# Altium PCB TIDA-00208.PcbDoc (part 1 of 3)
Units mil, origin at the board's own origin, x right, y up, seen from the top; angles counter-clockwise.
Board outline 4724.41 x 3937.01 mil, 4 copper layers (Top Layer, MidLayer1, MidLayer2, Bottom Layer), stack 90 mil thick; 243 components, 132 nets, 667 pads, 234 vias.
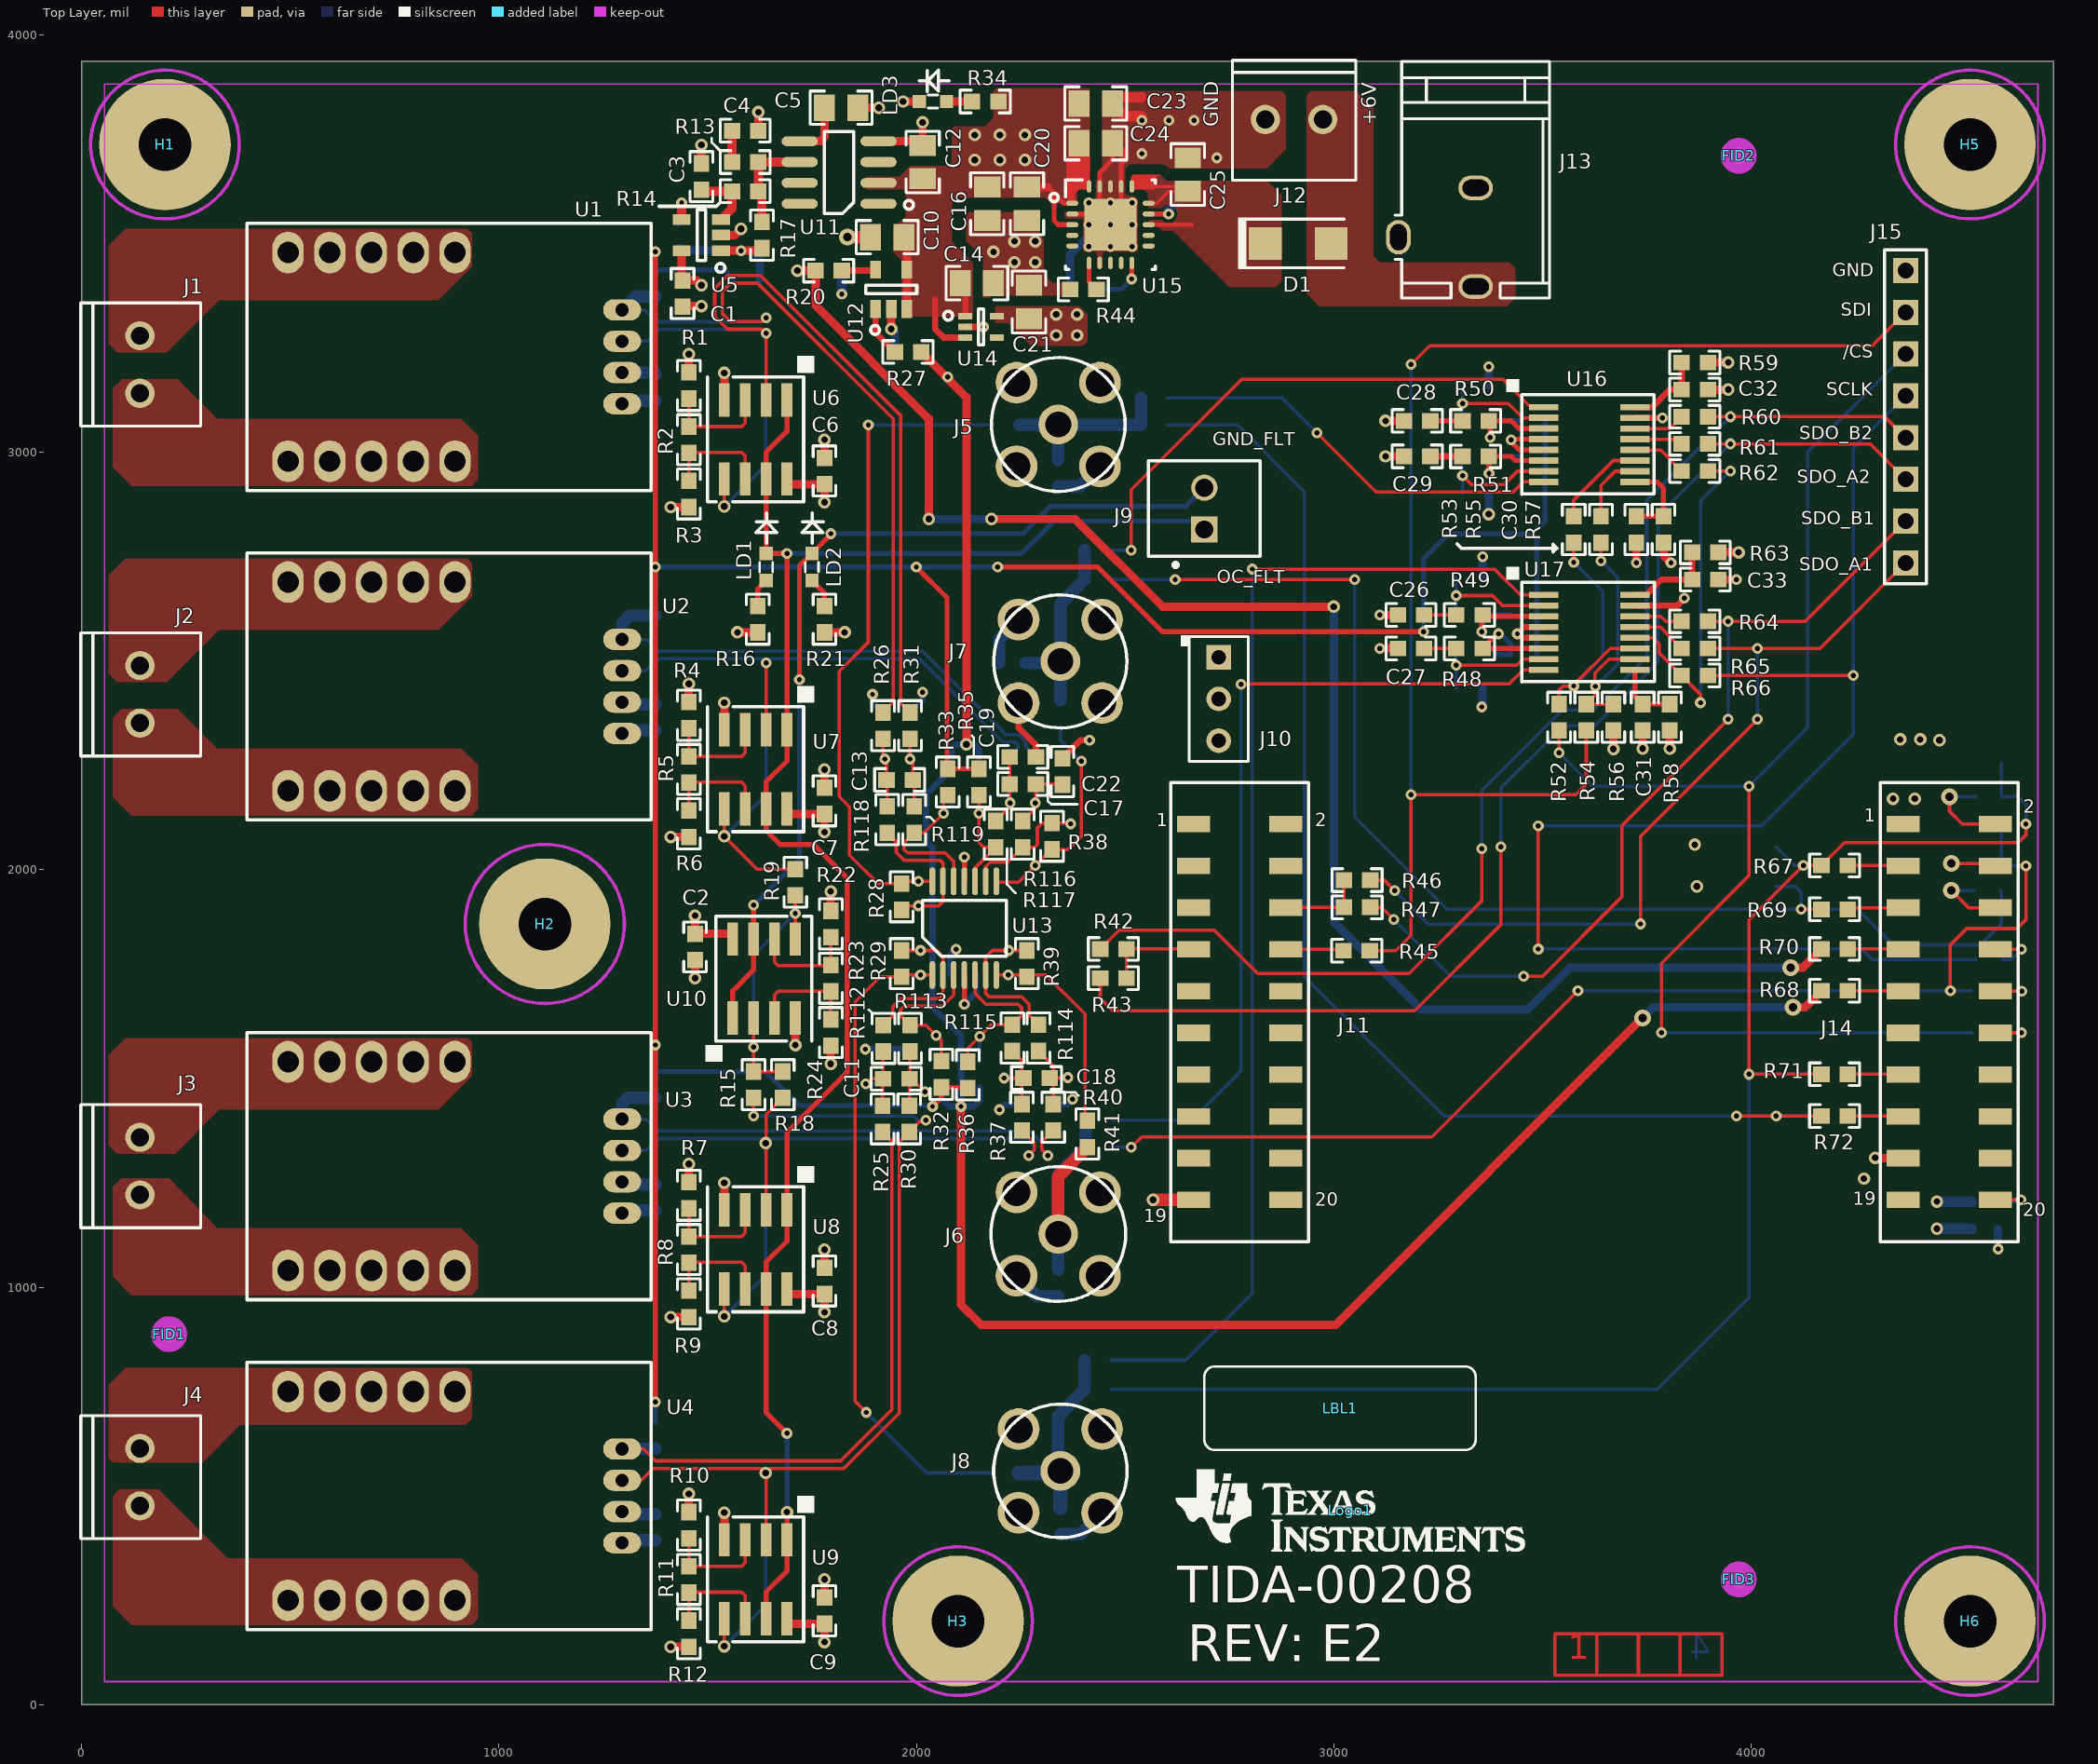
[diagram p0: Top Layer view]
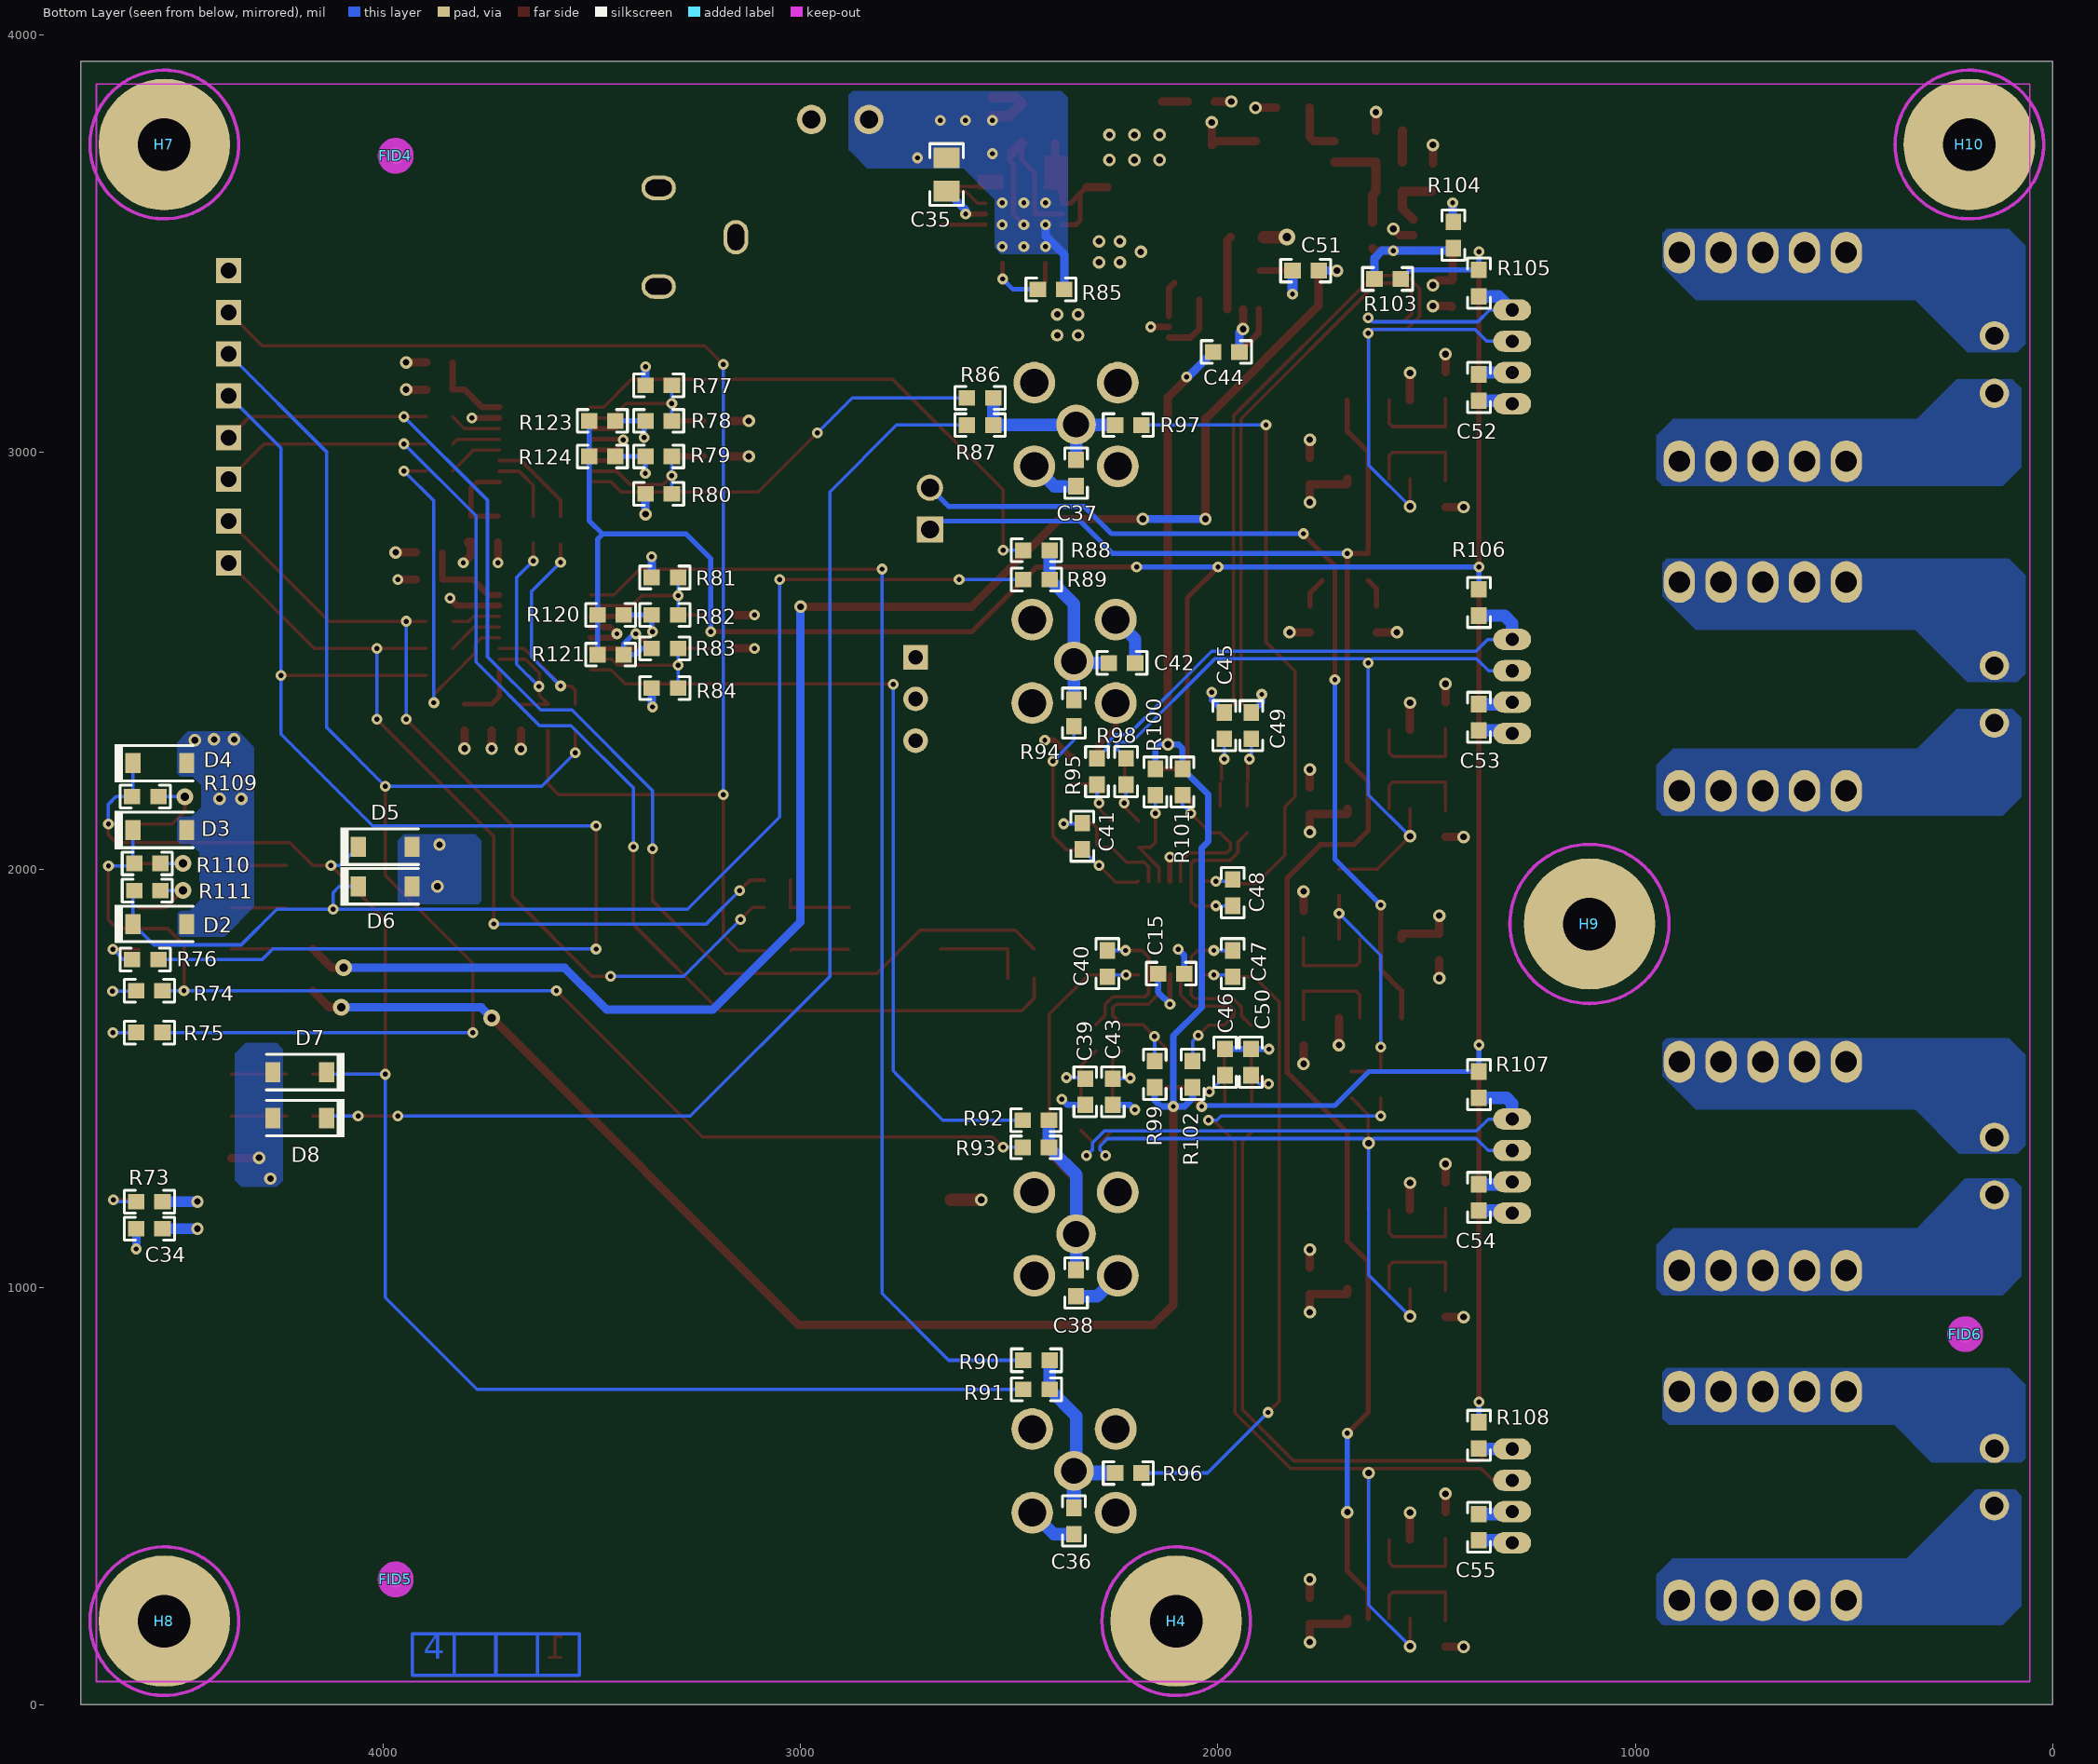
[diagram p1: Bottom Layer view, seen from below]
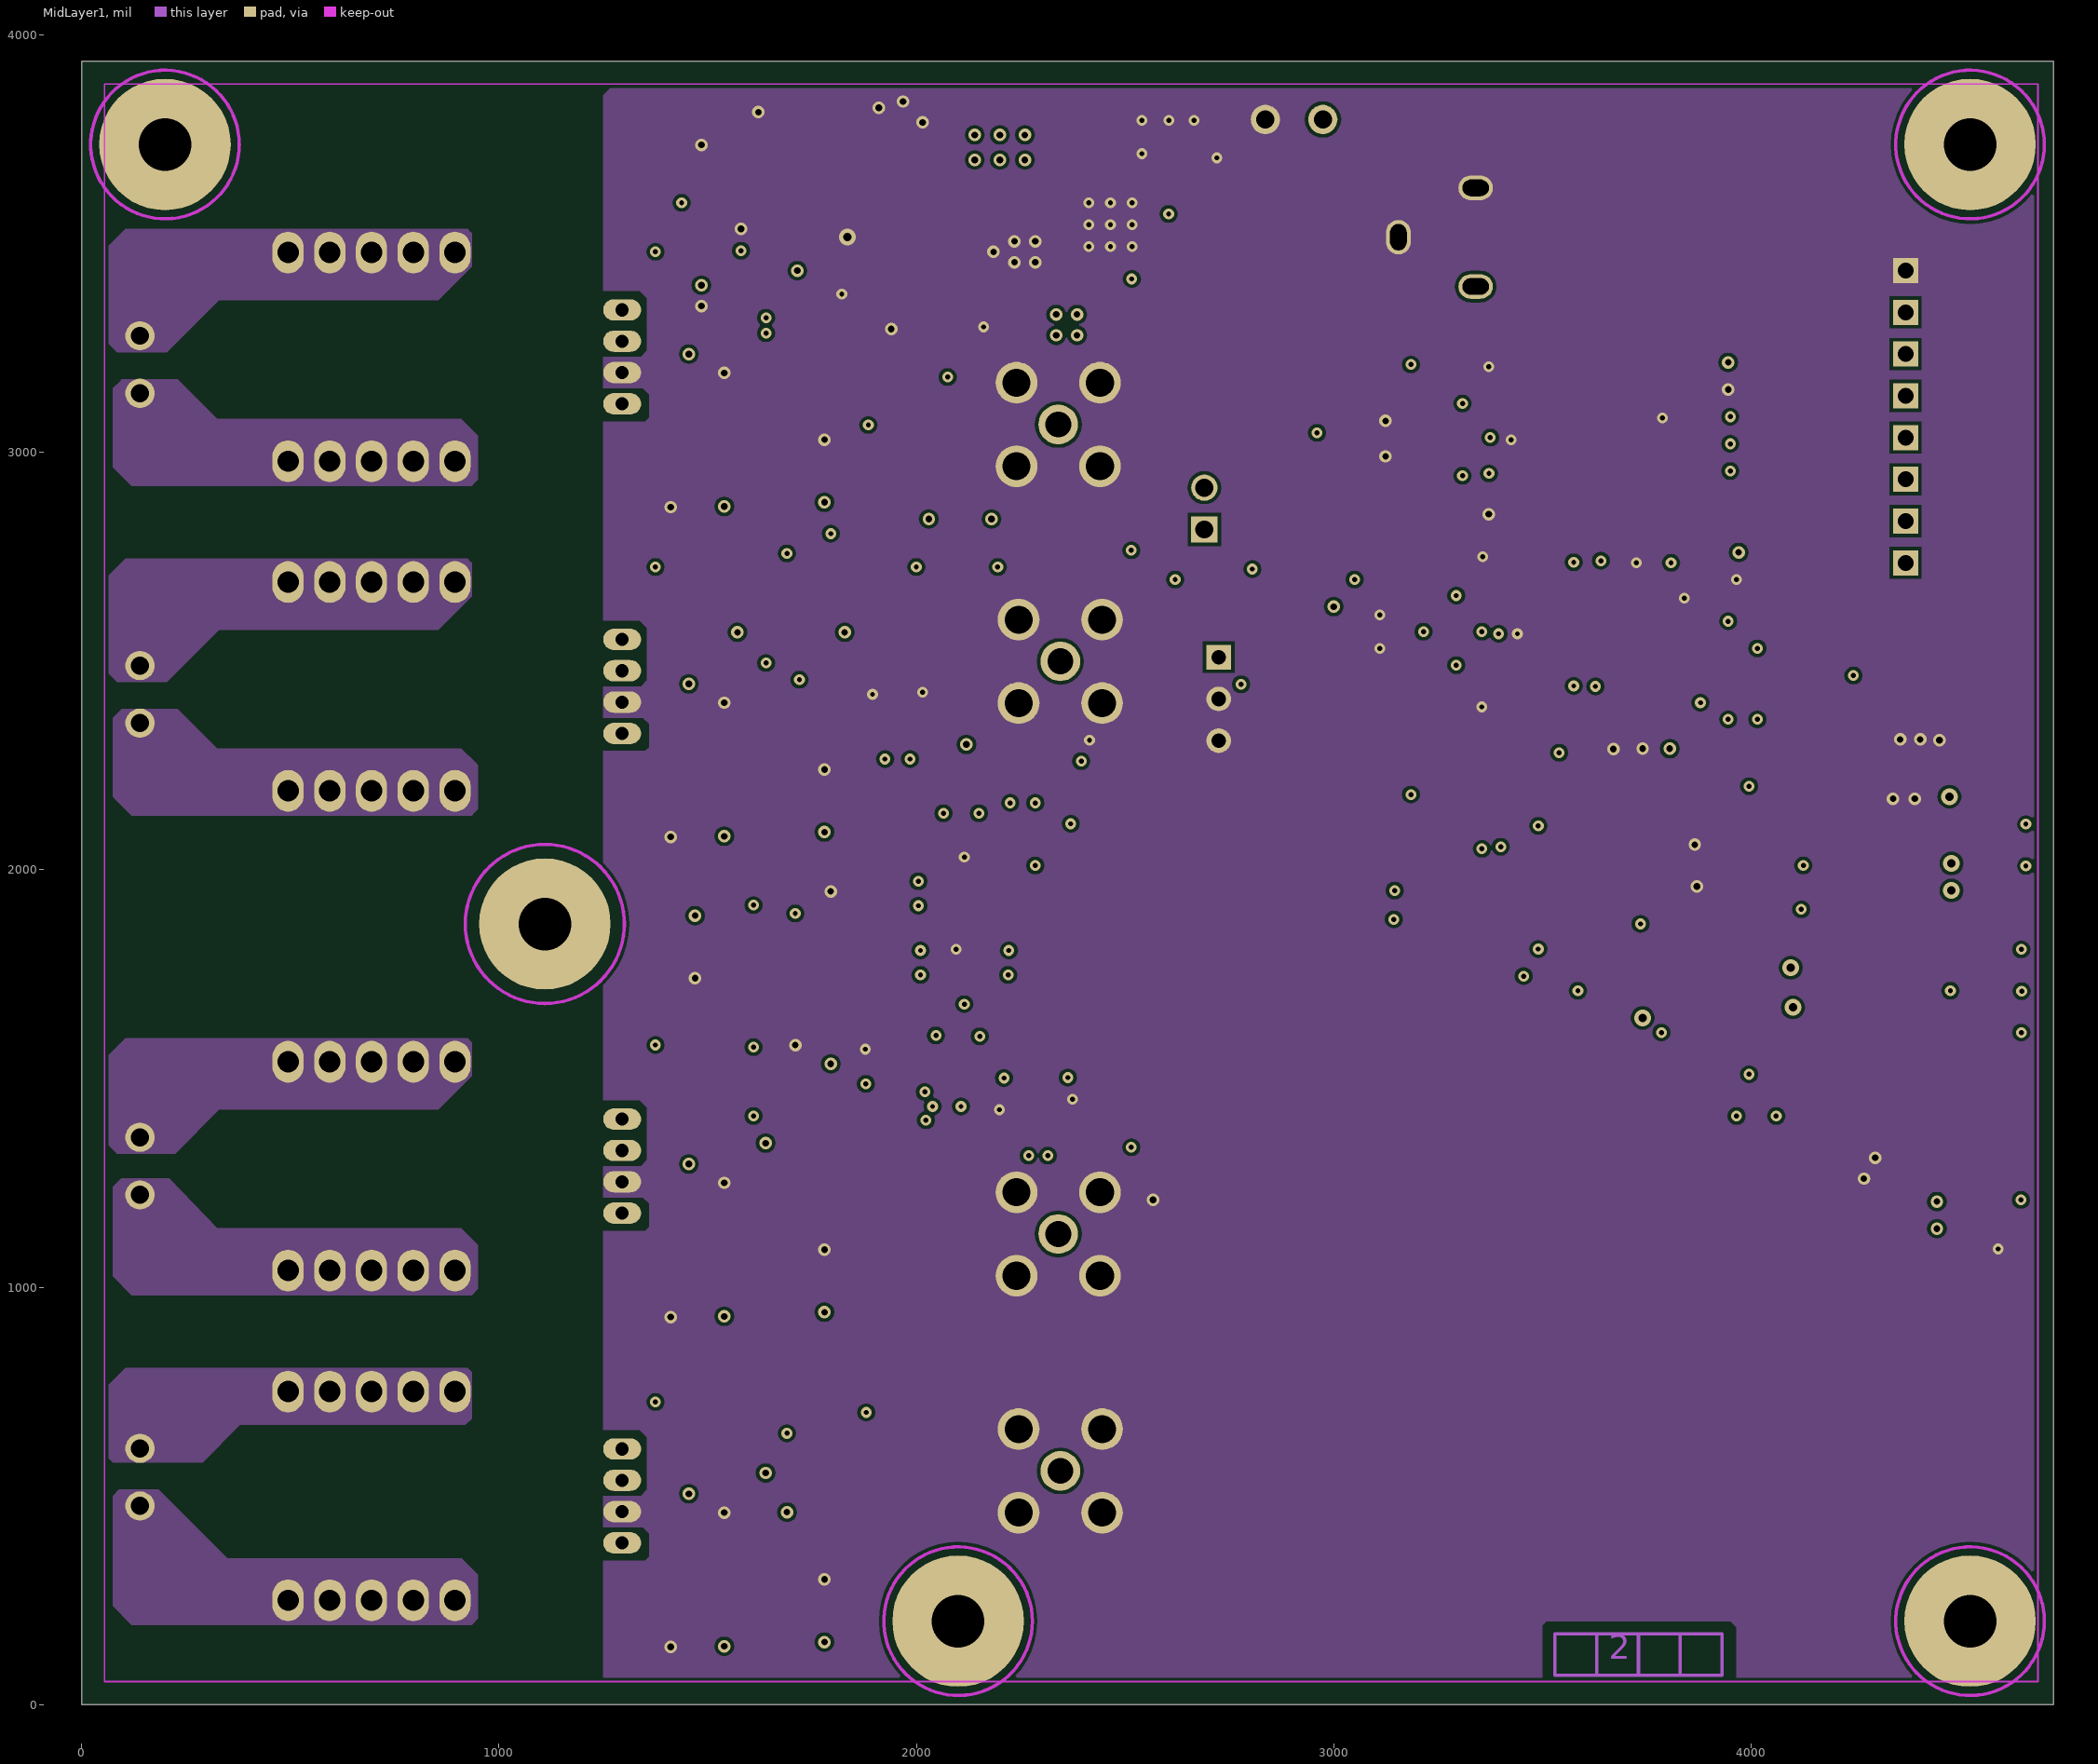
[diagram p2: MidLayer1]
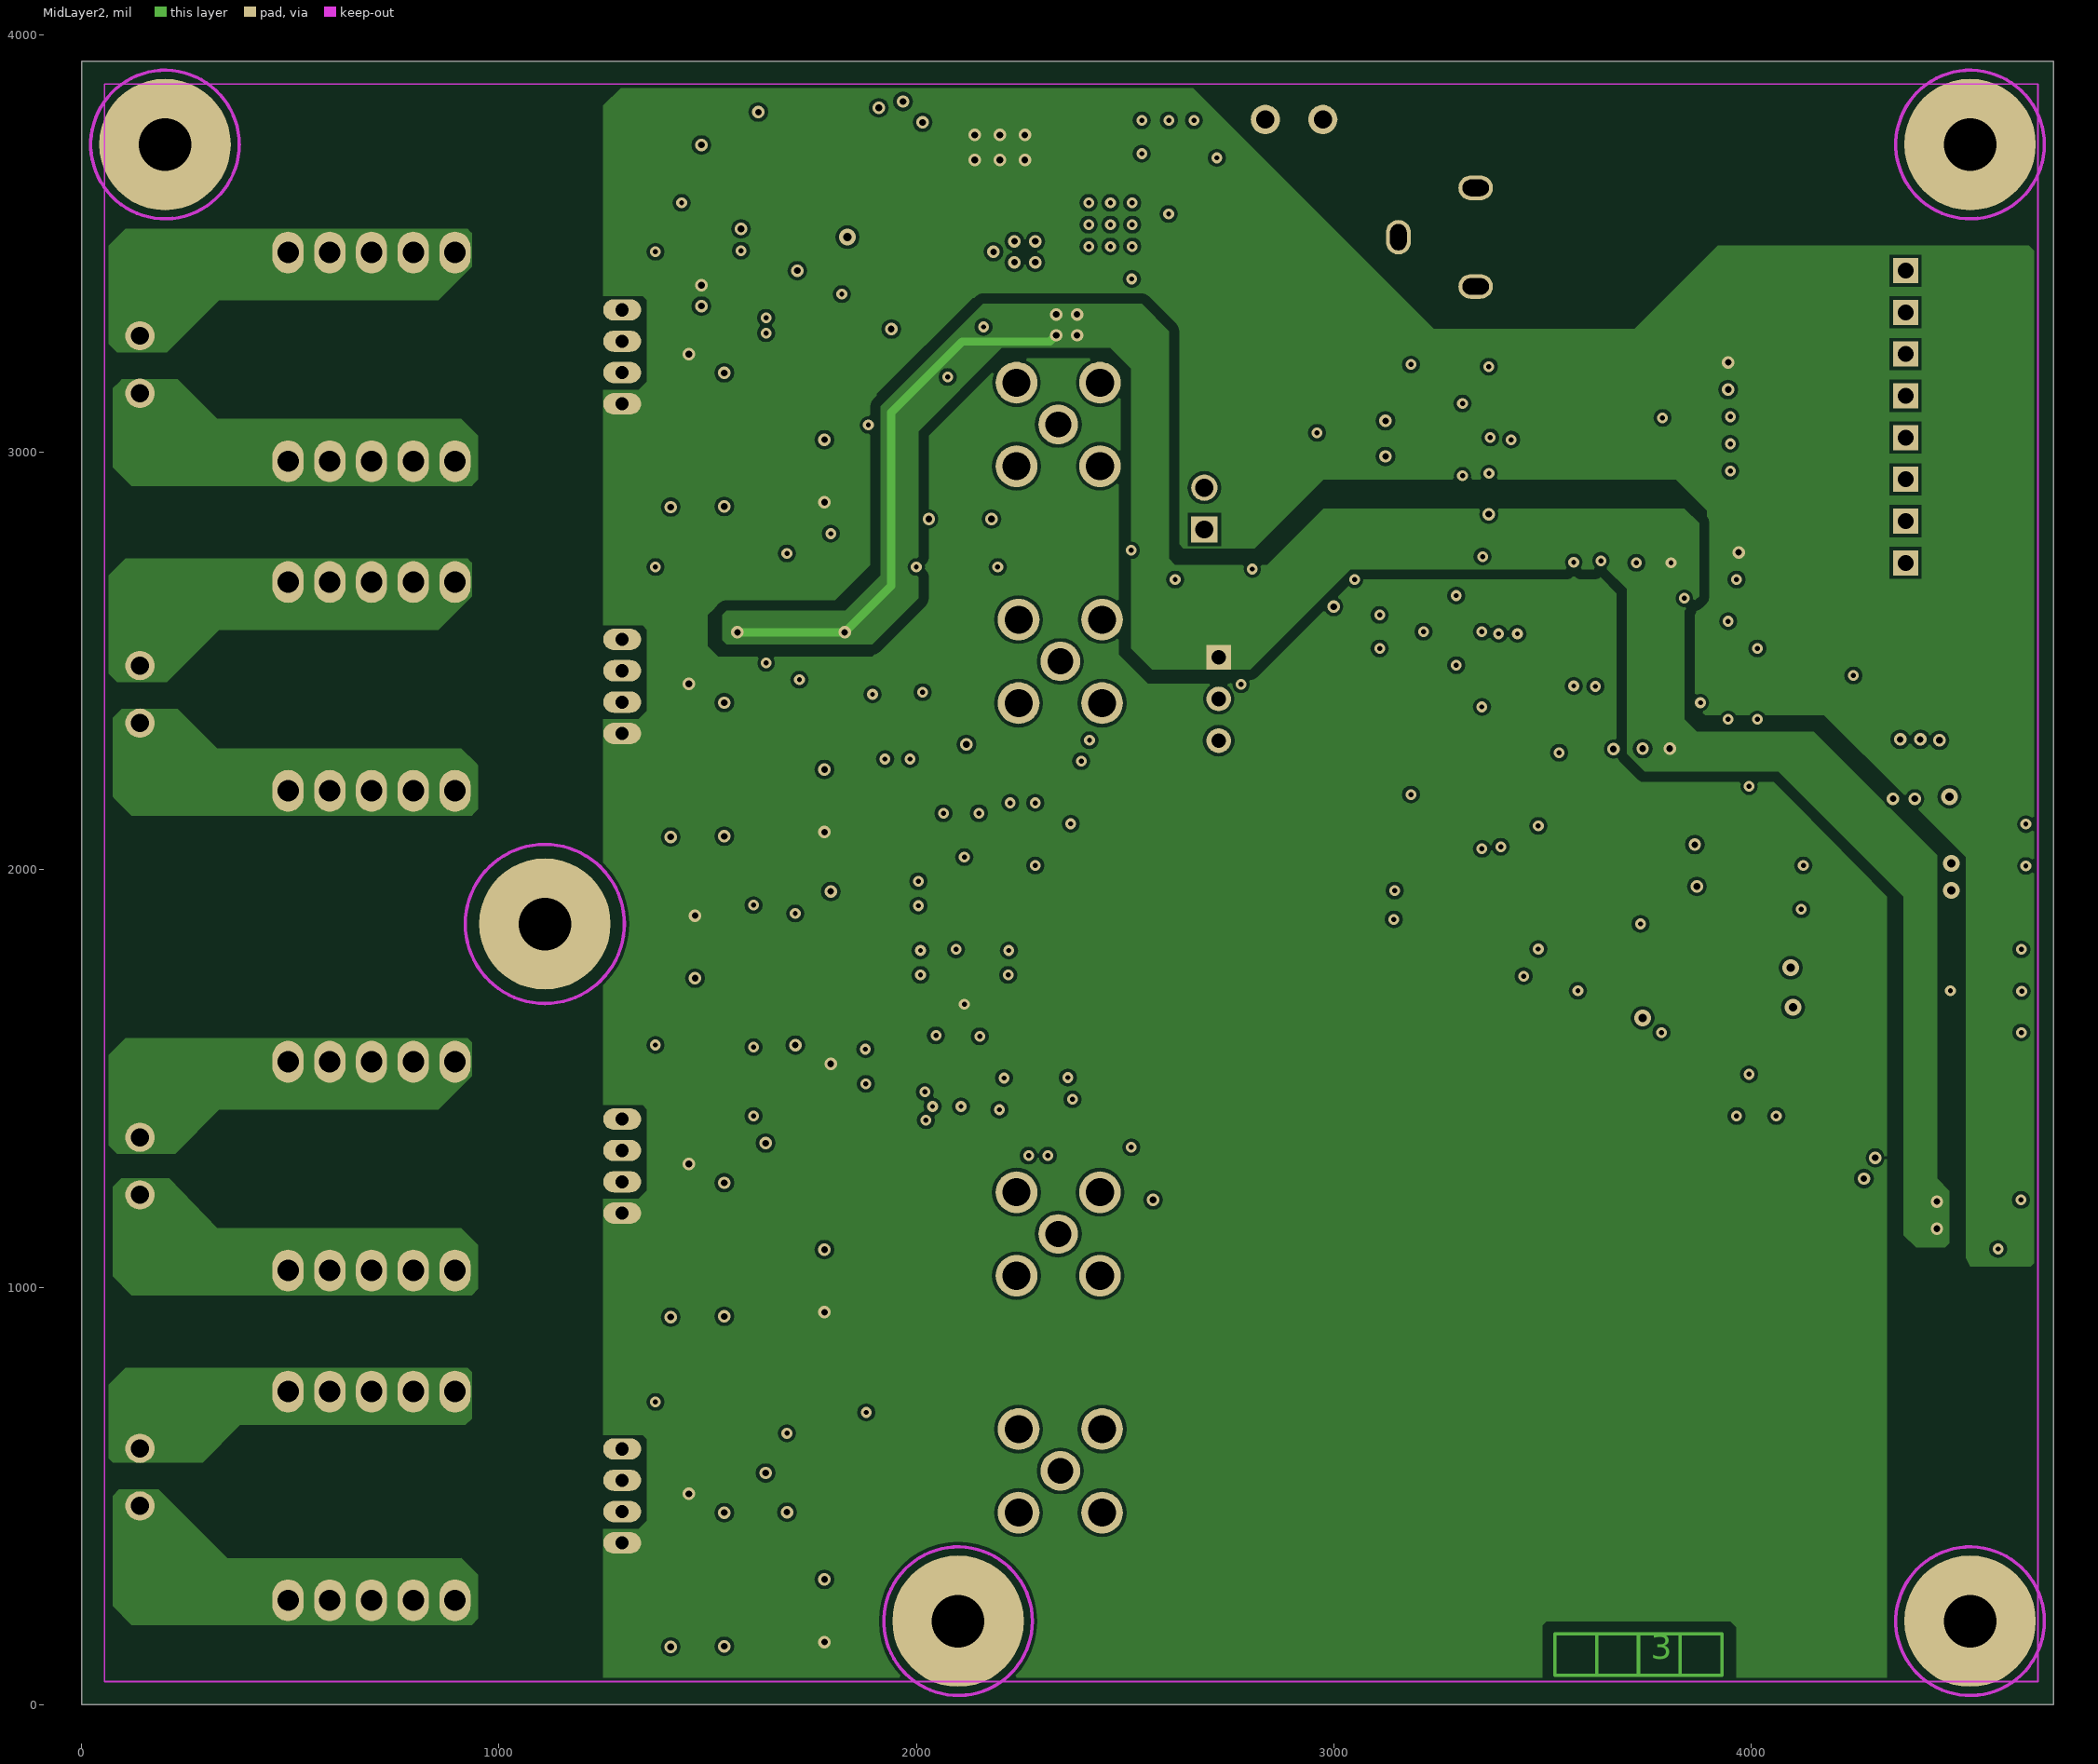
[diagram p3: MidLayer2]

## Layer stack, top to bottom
Top Layer: signal copper 1.4
Dielectric: core 59.2, FR-4, Dk 4.8
MidLayer1: signal copper 1.4
Dielectric: prepreg 12.6, FR-4, Dk 4.8
MidLayer2: signal copper 1.4
Dielectric: core 12.6, FR-4, Dk 4.8
Bottom Layer: signal copper 1.4

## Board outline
0,0 4724.41,0 4724.41,3937.01 0,3937.01

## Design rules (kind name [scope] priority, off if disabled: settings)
AcuteAngle [All] p1: minimum=4.50000000000000E+0001 checktracksonly=FALSE
AssemblyTestPointUsage [All] p1: valid=2
Clearance "Less Than 9 mils from PAD to PAD" [(InPadClass('Less than 9 Mil Clearance')) vs (InPadClass('All Pads'))] p1: gap=7
Clearance "SMT Pin Via" [IsVia vs IsSMTPin] p2: gap=8
Clearance "Via to Via" [IsVia vs IsVia] p3: gap=8
Clearance Clearance_Poly [InPolygon vs IsVia and IsVia and IsSMTPin and IsThruPin] p4: gap=15
Clearance "Poly to Poly" [InPolygon vs InPolygon] p5: gap=25
Clearance [All] p6: gap=8
ComponentClearance ComponentClearance_Shunt [InComponentClass('Header') vs InComponentClass('Shunt')] p1: gap=0 collisioncheckmode=3 verticalgap=0 showdistances=FALSE
ComponentClearance ComponentClearance_Logo [InComponentClass('Logo')] p2: gap=50 collisioncheckmode=3 verticalgap=10 showdistances=FALSE
ComponentClearance ComponentClearance_ScrewToNut [(HasFootprint('NY PMS 440 0025 PH')) vs (HasFootprint('Keystone_1902C'))] p3: gap=5 collisioncheckmode=3 verticalgap=10 showdistances=FALSE
ComponentClearance ComponentClearance_MountingHoles [InComponentClass('Mounting Holes')] p4: gap=250 collisioncheckmode=3 verticalgap=100000 showdistances=FALSE
ComponentClearance ComponentClearance_SmallPassives [HasFootprint('0201*') or HasFootprint('0402*') or HasFootprint('0508') or HasFootprint('0603*') or HasFootprint('0612') or HasFootprint('0805*') or HasFootprint('0815*') or HasFootprint('0830*') or HasFootprint('1206*') or HasFootprint('1210*') or HasFootprint('1808*') or HasFootprint('1812*') or HasFootprint('1825*') or HasFootprint('2010*') or HasFootprint('2220*') or HasFootprint('2225*') or HasFootprint('2512*') or HasFootprint('2728*') or HasFootprint('3518*') vs HasFootprint('0201*') or HasFootprint('0402*') or HasFootprint('0508') or HasFootprint('0603*') or HasFootprint('0612') or HasFootprint('0805*') or HasFootprint('0815*') or HasFootprint('0830*') or HasFootprint('1206*') or HasFootprint('1210*') or HasFootprint('1808*') or HasFootprint('1812*') or HasFootprint('1825*') or HasFootprint('2010*') or HasFootprint('2220*') or HasFootprint('2225*') or HasFootprint('2512*') or HasFootprint('2728*') or HasFootprint('3518*')] p5: gap=20 collisioncheckmode=3 verticalgap=10 showdistances=FALSE
ComponentClearance ComponentClearance_THtoSMT [IsThruComponent vs IsSMTComponent] p6: gap=100 collisioncheckmode=3 verticalgap=30 showdistances=FALSE
ComponentClearance ComponentClearance_THtoTH [IsThruComponent vs IsThruComponent] p7: gap=118.11 collisioncheckmode=3 verticalgap=30 showdistances=FALSE
ComponentClearance [All] p8: gap=40 collisioncheckmode=3 verticalgap=10 showdistances=FALSE
DiffPairsRouting DiffPair_CH3DiffPairsRouting [InDifferentialPair ('CH3')] p1: maxlimit=10 minlimit=10 mostfreqgap=10 maxuncoupledlength=500
DiffPairsRouting DiffPair_CH4DiffPairsRouting [InDifferentialPair ('CH4')] p2: maxlimit=10 minlimit=10 mostfreqgap=10 maxuncoupledlength=500
DiffPairsRouting DiffPair_CH2DiffPairsRouting [InDifferentialPair ('CH2')] p3: maxlimit=10 minlimit=10 mostfreqgap=10 maxuncoupledlength=500
DiffPairsRouting DiffPair_CH1DiffPairsRouting [InDifferentialPair ('CH1')] p4: maxlimit=10 minlimit=10 mostfreqgap=10 maxuncoupledlength=500
DiffPairsRouting [All] p5: maxlimit=100 minlimit=10 mostfreqgap=10 maxuncoupledlength=1000
FabricationTestPointUsage TestPointUsage [All] p1: valid=2 allowmultiple=FALSE
FabricationTestpoint Testpoint [All] p1: side=3 testpointundercomponent=TRUE minsize=40 maxsize=100 preferedsize=60 minholesize=0 maxholesize=40 preferedholesize=32 testpointgrid=1 allowsidetop=TRUE allowsidebottom=TRUE usegrid=TRUE gridtolerance=0.01
FanoutControl Fanout_LCC [IsLCC] p1: bgadir=Out bgaviamode=Centered fanoutstyle=Auto fanoutdirection=Alternating viagrid=1 // Fanout_LCC (Default Rule)
FanoutControl Fanout_BGA [IsBGA] p2: bgadir=Out bgaviamode=Centered fanoutstyle=Auto fanoutdirection=Alternating viagrid=1 // Fanout_BGA (Default Rule)
FanoutControl Fanout_Default [All] p4: bgadir=Out bgaviamode=Centered fanoutstyle=Auto fanoutdirection=Alternating viagrid=1 // Fanout_Default (Default Rule)
FanoutControl Fanout_Small [(CompPinCount < 5)] p5: bgadir=Out bgaviamode=Centered fanoutstyle=Auto fanoutdirection=OutThenIn viagrid=1 // Fanout_Small (Default Rule)
HoleSize [All] p1: absolutevalues=TRUE maxlimit=251 minlimit=8 maxpercent=80.000 minpercent=20.000
MatchedLengths DiffPair_CH3MatchedLengths [InDifferentialPair ('CH3')] p1: tolerance=500 checknetsindiffpair=TRUE checkdiffpairvsdiffpair=TRUE checkothers=TRUE
MatchedLengths DiffPair_CH4MatchedLengths [InDifferentialPair ('CH4')] p2: tolerance=500 checknetsindiffpair=TRUE checkdiffpairvsdiffpair=TRUE checkothers=TRUE
MatchedLengths DiffPair_CH2MatchedLengths [InDifferentialPair ('CH2')] p3: tolerance=500 checknetsindiffpair=TRUE checkdiffpairvsdiffpair=TRUE checkothers=TRUE
MatchedLengths DiffPair_CH1MatchedLengths [InDifferentialPair ('CH1')] p4: tolerance=500 checknetsindiffpair=TRUE checkdiffpairvsdiffpair=TRUE checkothers=TRUE
MinimumAnnularRing MinimumAnnularRing_ThermalPadVias [IsVia and InAnyComponent] p1: minimumring=6
MinimumAnnularRing [All] p2: minimumring=6
MinimumSolderMaskSliver MinimumSolderMaskSliver_Logo [InComponentClass('Logo') vs InComponentClass('Logo')] p1: minsoldermaskwidth=0.7
MinimumSolderMaskSliver [All] p2: minsoldermaskwidth=3.94
PlaneConnect [All] p1: planeconnectstyle=Relief reliefexpansion=10 reliefentries=4 reliefconductorwidth=10 reliefairgap=10
PolygonConnect [All] p1: connectstyle=Direct reliefconductorwidth=10 reliefentries=4 polygonreliefangle="90 Angle" airgapwidth=10
RoutingVias [All] p1: holewidth=12 width=26 viastyle="Through Hole" minholewidth=12 minwidth=26 maxholewidth=20 maxwidth=40
SMDToCorner [All] p1: distance=30000
SilkToSilkClearance [All] p1: silktosilkclearance=5
SilkscreenOverComponentPads [All] p1: minsilkscreentomaskgap=5
SolderMaskExpansion [All] p1: expansion=2.5
Width DiffPair_CH3Width [InDifferentialPair('CH3')] p1: maxlimit=100 minlimit=8 preferedwidth=8
Width DiffPair_CH4Width [InDifferentialPair('CH4')] p2: maxlimit=100 minlimit=8 preferedwidth=8
Width DiffPair_CH2Width [InDifferentialPair('CH2')] p3: maxlimit=100 minlimit=8 preferedwidth=8
Width DiffPair_CH1Width [InDifferentialPair('CH1')] p4: maxlimit=100 minlimit=8 preferedwidth=8
Width Width_PWR [InNetClass('PWR')] p5: maxlimit=100 minlimit=8 preferedwidth=15
Width [All] p6: maxlimit=100 minlimit=8 preferedwidth=8 checkconnectedcopper=TRUE
14 further rules are at their usual default settings.

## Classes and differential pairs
component class "Mounting Holes": H1 H2 H3 H5 H6
component class Logo: Logo1
component class Label: LBL1
component class FiducialMark: FID1 FID2 FID3 FID4 FID5 FID6
component class AssemblyNote: ZZ1 ZZ2 ZZ3 ZZ4

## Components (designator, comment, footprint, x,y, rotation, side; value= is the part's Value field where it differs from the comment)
C1 "C0603C104J4RACTU" 0603 1440,3380 r90 top (schematic designator C31)
C2 "C0603C104J4RACTU" 0603 1470,1815 r270 top (schematic designator C41)
C3 "C0603C104K8RACTU" 0603 1485,3660 r270 top (schematic designator C42)
C4 "EMK107BBJ106MA-T" 0603 1590,3770 r0 top (schematic designator C17)
C5 "C0805C105K8RACTU" 0805_HV 1820,3825 r0 top (schematic designator C15)
C6 "C0603C104J4RACTU" 0603 1780,2955 r90 top (schematic designator C54)
C7 "C0603C104J4RACTU" 0603 1780,2165 r90 top (schematic designator C40)
C8 "C0603C104J4RACTU" 0603 1780,1015 r90 top (schematic designator C14)
C9 "C0603C104J4RACTU" 0603 1780,225 r90 top (schematic designator C7)
C10 "C0805C105K8RACTU" 0805_HV 1930,3515 r180 top (schematic designator C28)
C11 "C0603H103J3GACTU" 0603 1952,1499 r180 top (schematic designator C47)
C12 "C0805C105K8RACTU" 0805_HV 2015,3695 r90 top (schematic designator C16)
C13 "C0603H103J3GACTU" 0603 1960,2215 r180 top (schematic designator C33)
C14 "C0805C105K8RACTU" 0805_HV 2145,3405 r0 top (schematic designator C18)
C15 "C0603C104J4RACTU" 0603 2112,1751 r0 bottom (schematic designator C2)
C16 "GRM21BR61C106KE15L" 0805_HV 2170,3595 r270 top (schematic designator C12)
C17 "C0603H103J3GACTU" 0603 2255,2205 r0 top (schematic designator C43)
C18 "C0603H103J3GACTU" 0603 2288,1501 r180 top (schematic designator C9)
C19 "C1608C0G1E562J" 0603 2255,2270 r0 top (schematic designator C45)
C20 "GRM21BR61C106KE15L" 0805_HV 2265,3595 r270 top (schematic designator C23)
C21 "C0805C105K8RACTU" 0805_HV 2270,3360 r90 top (schematic designator C19)
C22 "C1608C0G1E562J" 0603 2350,2235 r90 top (schematic designator C44)
C23 "GRM21BR61C106KE15L" 0805_HV 2430,3835 r0 top (schematic designator C22)
C24 "GRM21BR61C106KE15L" 0805_HV 2430,3740 r0 top (schematic designator C21)
C25 "GRM21BR61C106KE15L" 0805_HV 2650,3665 r90 top (schematic designator C5)
C26 "C1608X5R1E106M080AC" 0603 3185,2610 r180 top (schematic designator C4)
C27 "C1608X5R1E106M080AC" 0603 3185,2530 r0 top (schematic designator C10)
C28 "C1608X5R1E106M080AC" 0603 3200,3075 r180 top (schematic designator C25)
C29 "C1608X5R1E106M080AC" 0603 3200,2990 r0 top (schematic designator C26)
C30 "C1608X5R1E106M080AC" 0603 3725,2815 r270 top (schematic designator C27)
C31 "C1608X5R1E106M080AC" 0603 3740,2365 r270 top (schematic designator C11)
C32 "C1608X5R1E106M080AC" 0603 3865,3150 r0 top (schematic designator C24)
C33 "C1608X5R1E106M080AC" 0603 3890,2695 r0 top (schematic designator C3)
C34 "GRM188R71E105KA12D" 0603 4560,1140 r0 bottom (schematic designator C55)
C35 "C0805C105K8RACTU" 0805_HV 2650,3665 r270 bottom (schematic designator C20)
C36 "C0603C104J4RACTU" 0603 2345,440 r270 bottom (schematic designator C6)
C37 "C0603C104J4RACTU" 0603 2340,2950 r270 bottom (schematic designator C53)
C38 "C0603C104J4RACTU" 0603 2340,1010 r270 bottom (schematic designator C13)
C39 "C1608C0G1E562J" 0603 2318,1468 r270 bottom (schematic designator C35)
C40 "GRM1885C1E102JA01D" 0603 2265,1775 r90 bottom (schematic designator C8)
C41 "GRM1885C1E102JA01D" 0603 2325,2080 r90 bottom (schematic designator C34)
C42 "C0603C104J4RACTU" 0603 2230,2495 r180 bottom (schematic designator C39)
C43 "C1608C0G1E562J" 0603 2252,1468 r270 bottom (schematic designator C36)
C44 "C0603C104K8RACTU" 0603 1980,3240 r0 bottom (schematic designator C30)
C45 "C1608C0G1E562J" 0603 1985,2345 r90 bottom (schematic designator C52)
C46 "C1608C0G1E562J" 0603 1983,1539 r90 bottom (schematic designator C49)
C47 "GRM1885C1E102JA01D" 0603 1965,1775 r90 bottom (schematic designator C1)
C48 "GRM1885C1E102JA01D" 0603 1965,1945 r270 bottom (schematic designator C32)
C49 "C1608C0G1E562J" 0603 1920,2345 r90 bottom (schematic designator C51)
C50 "C1608C0G1E562J" 0603 1921,1539 r90 bottom (schematic designator C48)
C51 "C0603C104K8RACTU" 0603 1790,3435 r180 bottom (schematic designator C29)
C52 "GRM188R71E105KA12D" 0603 1375,3155 r270 bottom (schematic designator C38)
C53 "GRM188R71E105KA12D" 0603 1375,2365 r270 bottom (schematic designator C46)
C54 "GRM188R71E105KA12D" 0603 1375,1215 r270 bottom (schematic designator C37)
C55 "GRM188R71E105KA12D" 0603 1375,425 r270 bottom (schematic designator C50)
D1 "MBRA160T3G" SMA 2915,3500 r0 top
D2 "MMSZ5227B-7-F" SOD-123 4535,1870 r180 bottom
D3 "MMSZ5227B-7-F" SOD-123 4535,2095 r180 bottom
D4 "MMSZ5227B-7-F" SOD-123 4535,2255 r180 bottom
D5 "MMSZ5227B-7-F" SOD-123 3995,2055 r180 bottom
D6 "MMSZ5227B-7-F" SOD-123 3995,1960 r180 bottom
D7 "MMSZ5227B-7-F" SOD-123 4200,1515 r0 bottom
D8 "MMSZ5227B-7-F" SOD-123 4200,1405 r0 bottom
FID1 "Fiducial" Fiducial10-20 210,887.4 r90 top
FID2 "Fiducial" Fiducial10-20 3970,3710 r90 top (schematic designator FID3)
FID3 "Fiducial" Fiducial10-20 3970,300 r90 top (schematic designator FID2)
FID4 "Fiducial" Fiducial10-20 3970,3710 r90 bottom (schematic designator FID6)
FID5 "Fiducial" Fiducial10-20 3970,300 r90 bottom
FID6 "Fiducial" Fiducial10-20 210,887.4 r90 bottom (schematic designator FID4)
H1 "NY PMS 440 0025 PH" "NY PMS 440 0025 PH" 200,3737.01 r0 top (schematic designator H3)
H2 "NY PMS 440 0025 PH" "NY PMS 440 0025 PH" 1110,1870.08 r0 top (schematic designator H5)
H3 "NY PMS 440 0025 PH" "NY PMS 440 0025 PH" 2100,200 r0 top (schematic designator H1)
H4 "1902C" Keystone_1902C 2100,200 r180 bottom (schematic designator H6)
H5 "NY PMS 440 0025 PH" "NY PMS 440 0025 PH" 4524.41,3737.01 r0 top (schematic designator H2)
H6 "NY PMS 440 0025 PH" "NY PMS 440 0025 PH" 4524.41,200 r0 top (schematic designator H4)
H7 "1902C" Keystone_1902C 4524.41,3737.01 r180 bottom (schematic designator H9)
H8 "1902C" Keystone_1902C 4524.41,200 r180 bottom (schematic designator H7)
H9 "1902C" Keystone_1902C 1110,1870.08 r180 bottom (schematic designator H10)
H10 "1902C" Keystone_1902C 200,3737.01 r180 bottom (schematic designator H8)
J1 "1751248" CONN_1751248 140,3210 r270 top (schematic designator J7)
J2 "1751248" CONN_1751248 140,2420 r270 top (schematic designator J10)
J3 "1751248" CONN_1751248 140,1290 r270 top (schematic designator J5)
J4 "1751248" CONN_1751248 140,545 r270 top (schematic designator J1)
J5 "142-0701-201" Johnson_142-0701-20x 2340,3066.38 r0 top (schematic designator J12)
J6 "142-0701-201" Johnson_142-0701-20x 2340,1127.4 r0 top
J7 "142-0701-201" Johnson_142-0701-20x 2345,2498.98 r0 top (schematic designator J11)
J8 "142-0701-201" Johnson_142-0701-20x 2345,560 r0 top (schematic designator J2)
J9 "282834-2" TEC_282834-2 2690,2865 r90 top (schematic designator J8)
J10 "534237-1" CONN_534237-1 2724.41,2409.05 r90 top locked (schematic designator J3)
J11 "HEADER_NPTC202KFM" HEADER_NPTC202KFM 2774.41,1659.05 r270 top locked (schematic designator J2_J6)
J12 "1751248" CONN_1751248 2905,3797 r180 top (schematic designator J9)
J13 "PJ-102A" CONN_PJ-102A 3340,3515 r90 top (schematic designator J4)
J14 "HEADER_NPTC202KFM" HEADER_NPTC202KFM 4474.41,1659.05 r270 top locked (schematic designator J5_J1)
J15 "HEADER_1X8" HDR100_1X8 4370,2735 r90 top (schematic designator J14)
LBL1 "Size: 0.65\" x 0.20 \"" Label_650x200 3015,710 r180 top
LD1 "LED_LG L29K-G2J1-24-Z" LED0603AA 1640,2725 r270 top
LD2 "LED_LG L29K-G2J1-24-Z" LED0603AA 1750,2725 r270 top (schematic designator LD6)
LD3 "LED_LG L29K-G2J1-24-Z" LED0603AA 2040,3840 r0 top (schematic designator LD2)
Logo1 "Texas Instruments" TI_Stacked_SolderMask_Small 3040,465 r0 top
R1 "RC0603FR-073K3L" 0603 1455,3160 r90 top (schematic designator R98)
R2 "CRCW060320K0FKEA" 0603 1455,3030 r90 top (schematic designator R99)
R3 "RC0603FR-073K3L" 0603 1455,2900 r90 top (schematic designator R100)
R4 "RC0603FR-073K3L" 0603 1455,2370 r90 top (schematic designator R41)
R5 "CRCW060320K0FKEA" 0603 1455,2240 r90 top (schematic designator R44)
R6 "RC0603FR-073K3L" 0603 1455,2110 r90 top (schematic designator R50)
R7 "RC0603FR-073K3L" 0603 1455,1220 r90 top (schematic designator R19)
R8 "CRCW060320K0FKEA" 0603 1455,1090 r90 top (schematic designator R20)
R9 "RC0603FR-073K3L" 0603 1455,960 r90 top (schematic designator R22)
R10 "RC0603FR-073K3L" 0603 1455,430 r90 top (schematic designator R8)
R11 "CRCW060320K0FKEA" 0603 1455,300 r90 top (schematic designator R9)
R12 "RC0603FR-073K3L" 0603 1455,170 r90 top (schematic designator R11)
R13 "RC0603FR-071KL" 0603 1590,3695 r0 top (schematic designator R23)
R14 "CRCW06030000Z0EA" 0603 1590,3625 r0 top (schematic designator R72)
R15 "CRCW06031K00JNEA" 0603 1610,1485 r90 top (schematic designator R43)
R16 "CRCW060310K0JNEA" 0603 1620,2600 r270 top (schematic designator R7)
R17 "CRCW06030000Z0EA" 0603 1630,3520 r90 top (schematic designator R88)
R18 "CRCW06031K00JNEA" 0603 1680,1485 r90 top (schematic designator R48)
R19 "CRCW06031K00JNEA" 0603 1710,1970 r270 top (schematic designator R49)
R20 "CRCW06030000Z0EA" 0603 1790,3435 r0 top (schematic designator R81)
R21 "CRCW060310K0JNEA" 0603 1780,2600 r270 top (schematic designator R40)
R22 "RC0603FR-073K3L" 0603 1795,1870 r270 top (schematic designator R51)
R23 "CRCW060320K0FKEA" 0603 1795,1740 r270 top (schematic designator R45)
R24 "RC0603FR-073K3L" 0603 1795,1610 r270 top (schematic designator R42)
R25 "CRCW06031K50FKEA" 0603 1919,1403 r90 top (schematic designator R3)
R26 "CRCW06031K50FKEA" 0603 1920,2345 r270 top (schematic designator R91)
R27 "CRCW06030000Z0EA" 0603 1980,3240 r180 top (schematic designator R84)
R28 "CRCW06032K00FKEA" 0603 1965,1935 r90 top (schematic designator R89)
R29 "CRCW06032K00FKEA" 0603 1965,1775 r270 top (schematic designator R1)
R30 "CRCW06031K50FKEA" 0603 1983,1403 r90 top (schematic designator R2)
R31 "CRCW06031K50FKEA" 0603 1985,2345 r270 top (schematic designator R92)
R32 "CRCW06032K00FKEA" 0603 2060,1510 r90 top (schematic designator R82)
R33 "CRCW06032K00FKEA" 0603 2075,2210 r270 top (schematic designator R96)
R34 "CRCW060310K0JNEA" 0603 2165,3840 r0 top (schematic designator R85)
R35 "CRCW06032K00FKEA" 0603 2150,2210 r270 top (schematic designator R79)
R36 "CRCW06032K00FKEA" 0603 2123,1508.5 r90 top (schematic designator R76)
R37 "CRCW06031K50FKEA" 0603 2253,1407 r90 top (schematic designator R13)
R38 "CRCW06032K00FKEA" 0603 2325,2080 r270 top (schematic designator R33)
R39 "CRCW06032K00FKEA" 0603 2265,1775 r270 top (schematic designator R12)
R40 "CRCW06031K50FKEA" 0603 2328,1407 r90 top (schematic designator R14)
R41 "RT0603BRD0710RL" 0603 2410,1367 r270 top (schematic designator R17)
R42 "CRCW06030000Z0EA" 0603 2472,1810 r0 top (schematic designator R103)
R43 "CRCW06030000Z0EA" 0603 2472,1740 r0 top (schematic designator R102)
R44 "CRCW06030000Z0EA" 0603 2400,3390 r0 top (schematic designator R86)
R45 "CRCW06030000Z0EA" 0603 3055,1806 r180 top (schematic designator R61)
R46 "CRCW06030000Z0EA" 0603 3056,1975 r180 top (schematic designator R63)
R47 "CRCW06030000Z0EA" 0603 3056,1910 r180 top (schematic designator R66)
R48 "ERJ-3RSFR10V" 0603 3325,2530 r180 top (schematic designator R39)
R49 "ERJ-3RSFR10V" 0603 3325,2610 r0 top (schematic designator R10)
R50 "ERJ-3RSFR10V" 0603 3340,3075 r0 top (schematic designator R15)
R51 "ERJ-3RSFR10V" 0603 3340,2990 r180 top (schematic designator R29)
R52 "CRCW060347R0JNEA" 0603 3540,2365 r270 top (schematic designator R37)
R53 "CRCW06030000Z0EA" 0603 3575,2815 r90 top (schematic designator R28)
R54 "CRCW060347R0JNEA" 0603 3605,2365 r270 top (schematic designator R46)
R55 "CRCW06030000Z0EA" 0603 3640,2815 r90 top (schematic designator R31)
R56 "CRCW0603100KFKEA" 0603 3670,2365 r90 top (schematic designator R47)
R57 "CRCW06030000Z0EA" 0603 3790,2815 r270 top (schematic designator R32)
R58 "CRCW06030000Z0EA" 0603 3805,2365 r270 top (schematic designator R52)
R59 "CRCW06030000Z0EA" 0603 3865,3215 r0 top (schematic designator R4)
R60 "CRCW060347R0JNEA" 0603 3865,3085 r0 top (schematic designator R25)
R61 "CRCW060347R0JNEA" 0603 3865,3020 r0 top (schematic designator R26)
R62 "CRCW06030000Z0EA" 0603 3865,2955 r180 top (schematic designator R27)
R63 "CRCW06030000Z0EA" 0603 3890,2760 r0 top (schematic designator R5)
R64 "CRCW060347R0JNEA" 0603 3865,2595 r0 top (schematic designator R16)
R65 "CRCW060347R0JNEA" 0603 3865,2530 r0 top (schematic designator R18)
R66 "CRCW060347R0JNEA" 0603 3865,2465 r0 top (schematic designator R21)
R67 "CRCW06030000Z0EA" 0603 4200,2010 r180 top (schematic designator R36)
R68 "CRCW06030000Z0EA" 0603 4200,1710 r0 top (schematic designator R78)
R69 "CRCW06030000Z0EA" 0603 4200,1905 r0 top (schematic designator R62)
R70 "CRCW06030000Z0EA" 0603 4200,1810 r0 top (schematic designator R64)
R71 "CRCW06030000Z0EA" 0603 4200,1510 r180 top (schematic designator R104)
R72 "CRCW06030000Z0EA" 0603 4200,1410 r180 top (schematic designator R101)
R73 "CRCW06030000Z0EA" 0603 4560,1205 r180 bottom (schematic designator R53)
R74 "CRCW06030000Z0EA" 0603 4560,1710 r0 bottom (schematic designator R67)
R75 "CRCW06030000Z0EA" 0603 4560,1610 r0 bottom (schematic designator R68)
R76 "CRCW06030000Z0EA" 0603 4570,1785 r0 bottom (schematic designator R65)
R77 "CRCW06030000Z0EA" 0603 3340,3160 r0 bottom (schematic designator R24)
R78 "CRCW06030000Z0EA" 0603 3340,3075 r0 bottom (schematic designator R106)
R79 "CRCW06030000Z0EA" 0603 3340,2990 r0 bottom (schematic designator R108)
R80 "CRCW06030000Z0EA" 0603 3340,2900 r0 bottom (schematic designator R30)
R81 "CRCW06030000Z0EA" 0603 3325,2700 r0 bottom (schematic designator R59)
R82 "CRCW06030000Z0EA" 0603 3325,2610 r0 bottom (schematic designator R105)
R83 "CRCW06030000Z0EA" 0603 3325,2530 r0 bottom (schematic designator R107)
R84 "CRCW06030000Z0EA" 0603 3325,2435 r0 bottom (schematic designator R60)
R85 "CRCW06030000Z0EA" 0603 2400,3390 r180 bottom (schematic designator R87)
R86 "CRCW06030000Z0EA" 0603 2570,3130 r0 bottom (schematic designator R93)
R87 "CRCW06030000Z0EA" 0603 2570,3065 r0 bottom (schematic designator R94)
R88 "CRCW06030000Z0EA" 0603 2435,2765 r0 bottom (schematic designator R74)
R89 "CRCW06030000Z0EA" 0603 2435,2695 r0 bottom (schematic designator R56)
R90 "CRCW06030000Z0EA" 0603 2435,825 r0 bottom (schematic designator R57)
R91 "CRCW06030000Z0EA" 0603 2435,755 r0 bottom (schematic designator R58)
R92 "CRCW06030000Z0EA" 0603 2436.5,1400 r0 bottom (schematic designator R54)
R93 "CRCW06030000Z0EA" 0603 2436.5,1335 r0 bottom (schematic designator R55)
R94 "RT0603BRD0710RL" 0603 2345,2375 r90 bottom (schematic designator R38)
R95 "CRCW06031K50FKEA" 0603 2290,2235 r270 bottom (schematic designator R35)
R96 "RT0603BRD0710RL" 0603 2215,555 r0 bottom (schematic designator R6)
R97 "RT0603BRD0710RL" 0603 2215,3065 r0 bottom (schematic designator R95)
R98 "CRCW06031K50FKEA" 0603 2220,2235 r270 bottom (schematic designator R34)
R99 "CRCW06032K00FKEA" 0603 2151.54,1510 r90 bottom (schematic designator R77)
R100 "CRCW06032K00FKEA" 0603 2150,2210 r270 bottom (schematic designator R80)
R101 "CRCW06032K00FKEA" 0603 2085,2210 r270 bottom (schematic designator R97)
R102 "CRCW06032K00FKEA" 0603 2061,1510 r90 bottom (schematic designator R83)
R103 "CRCW06030000Z0EA" 0603 1593.5,3415 r0 bottom (schematic designator R71)
R104 "CRCW06030000Z0EA" 0603 1436,3520 r90 bottom (schematic designator R70)
R105 "CRCW06030000Z0EA" 0603 1375,3405 r90 bottom (schematic designator R90)
R106 "CRCW06030000Z0EA" 0603 1375,2640 r90 bottom (schematic designator R73)
R107 "CRCW06030000Z0EA" 0603 1375,1485 r90 bottom (schematic designator R69)
R108 "CRCW06030000Z0EA" 0603 1375,645 r90 bottom (schematic designator R75)
R109 "CRCW06030000Z0EA" 0603 4570,2175 r180 bottom
R110 "CRCW06030000Z0EA" 0603 4565,2015 r180 bottom
R111 "CRCW06030000Z0EA" 0603 4565,1950 r180 bottom
R112 "CRCW06030000Z0EA" 0603 1921,1596 r270 top
R113 "CRCW06030000Z0EA" 0603 1985,1596 r270 top
R114 "CRCW06030000Z0EA" 0603 2293,1597 r270 top
R115 "CRCW06030000Z0EA" 0603 2230,1597 r270 top
R116 "CRCW06030000Z0EA" 0603 2255,2085 r90 top
R117 "CRCW06030000Z0EA" 0603 2190,2085 r90 top
R118 "CRCW06030000Z0EA" 0603 1930,2120 r90 top
R119 "CRCW06030000Z0EA" 0603 1995,2120 r90 top
R120 "CRCW06030000Z0EA" 0603 3455,2610 r0 bottom
R121 "CRCW06030000Z0EA" 0603 3455,2515 r0 bottom
R123 "CRCW06030000Z0EA" 0603 3475,3075 r0 bottom
R124 "CRCW06030000Z0EA" 0603 3475,2990 r0 bottom
U1 "SENSOR_CKSR X-NP" "CKSR X-NP" 895,3228.35 r0 top (schematic designator U13)
U2 "SENSOR_CKSR X-NP" "CKSR X-NP" 895,2438.98 r0 top (schematic designator U14)
U3 "SENSOR_CKSR X-NP" "CKSR X-NP" 895,1290 r0 top (schematic designator U7)
U4 "SENSOR_CKSR X-NP" "CKSR X-NP" 895,500 r0 top (schematic designator U3)
U5 "OPA322AIDBVR" DBV0005A_N 1485,3520 r180 top (schematic designator U12)
U6 "TLC372" SO8 1615,3030 r270 top (schematic designator U17)
U7 "TLC372" SO8 1615,2240 r270 top (schematic designator U15)
U8 "TLC372" SO8 1615,1090 r270 top
U9 "TLC372" SO8 1615,300 r270 top (schematic designator U4)
U10 "TLC372" SO8 1635,1740 r90 top (schematic designator U16)
U11 "REF5025AID" D0008A_N 1815,3670 r180 top (schematic designator U9)
U12 "REF2033DBV" DBV0005A_N 1940,3390 r90 top (schematic designator U6)
U13 "OPA4322AIPW" PW0014A_N 2115,1860 r90 top (schematic designator U1)
U14 "TLV70033DCKR" DCK0005A_N 2155,3300 r0 top (schematic designator U10)
U15 "TPS7A4700RGW" RGW0020A 2465,3545 r0 top (schematic designator U5)
U16 "ADS7853" PW16 3610,3020 r0 top (schematic designator U11)
U17 "ADS7853" PW16 3610,2570 r0 top (schematic designator U2)
ZZ1 "These assemblies must be clean and free from flux and all contaminants. Use of no clean flux is not acceptable." AssemblyNote 315,4475 r0 top (schematic designator ZZ3)
ZZ2 "This Assembly Note is for PCB labels only" AssemblyNoteLabel 320,4640 r0 top (schematic designator ZZ1)
ZZ3 "These assemblies are ESD sensitive, ESD precautions shall be observed." AssemblyNote 320,4560 r0 top (schematic designator ZZ2)
ZZ4 "These assemblies must comply with workmanship standards IPC-A-610 Class 2, unless otherwise specified." AssemblyNote 320,4380 r0 top

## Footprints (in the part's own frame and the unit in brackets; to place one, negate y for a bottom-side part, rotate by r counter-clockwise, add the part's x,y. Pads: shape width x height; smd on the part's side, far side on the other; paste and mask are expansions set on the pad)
0603 [mm] "0603 from SM-752 data"
  rect 1x0.95 smd: 1(-0.8,0) 2(0.8,0)
  silkscreen extent -1.52,-0.69 1.52,0.69, body extent -0.87,-0.47 0.87,0.47, height 0.85
0805_HV [mil] "0805 with 30mil clearance between pads"
  rect 50x63 smd: 1(-40,0) 2(40,0)
  silkscreen extent -74,-40 74,40, body extent -43,-29 43,29, height 43
AssemblyNote [mil] "Assembly Note"
AssemblyNoteLabel [mil] "Assembly Note for PCB Labels"
"CKSR X-NP" [mm] "CURRENT SENSOR MOD"
  oval 1.9x2.54 hole 1.3: 1(-0.005,-6.35) 2(-2.545,-6.35) 3(-5.085,-6.35) 4(-7.625,-6.35) 5(-10.165,-6.35) 6(-10.165,6.35) 7(-7.625,6.35) 8(-5.085,6.35) 9(-2.545,6.35) 10(-0.005,6.35)
  oval 2.3x1.3 hole 0.8: 11(10.165,2.857) 12(10.165,0.953) 13(10.165,-0.953) 14(10.165,-2.857)
  silkscreen extent -12.66,-8.13 11.94,8.13, body extent -12.66,-6.7 9.25,6.7, height 16
CONN_534237-1 [mm] "TE Connectivity"
  rect 1.5x1.5 hole 0.889: 1(2.54,0)
  round 1.5 hole 0.889: 2(0,0) 3(-2.54,0)
  silkscreen extent -3.8,-1.8 3.88,2.3, body extent -3.81,-1.78 3.81,1.78, height 8.65
CONN_1751248 [mil] "Phoenix Contact"
  round 70 hole 43.31: 1(-68.9,0) 2(68.9,0)
  silkscreen extent -148,-142 148,146, body extent -148,-142 148,146, height 335
CONN_PJ-102A [mm] "CUI INC"
  oval 1.5x2.1 hole 1 slot 1.6 at 90 deg: 1(-3,0) 2(3,0)
  oval 2.1x1.5 hole 1 slot 1.6 at 0 deg: 3(0,4.7)
  silkscreen extent -3.7,-4.5 10.7,4.9, body extent -3.7,-4.5 10.7,4.9, height 11.02
D0008A_N [mm] "SOIC, 8-Leads, Body 4.9x3.9mm, Pitch 1.27mm, IPC Medium Density"
  oval 2.2x0.6 smd: 1(-2.4,1.905) 2(-2.4,0.635) 3(-2.4,-0.635) 4(-2.4,-1.905) 5(2.4,-1.905) 6(2.4,-0.635) 7(2.4,0.635) 8(2.4,1.905)
  silkscreen extent -0.9,-2.5 0.9,2.5, body extent -3,-2.45 3,2.45, height 1.63
DBV0005A_N [mm] "SOT23, 5-Leads, Body 2.9x1.6mm, Pitch 0.95mm, Lead Span 2.8mm, IPC Medium Density"
  rect 1.1x0.65 smd: 1(-1.2,0.95) 2(-1.2,0) 3(-1.2,-0.95) 4(1.2,-0.95) 5(1.2,0.95)
  silkscreen extent -0.25,-1.55 0.25,1.55, body extent -1.42,-1.46 1.42,1.46, height 1.08
DCK0005A_N [mm] "SOT353, 5-Leads, Body 2x1.3mm, Pitch 0.65mm, Lead Span 2.1mm, IPC Medium Density"
  rect 0.85x0.4 smd: 1(-0.95,0.65) 2(-0.95,0) 3(-0.95,-0.65) 4(0.95,-0.65) 5(0.95,0.65)
  silkscreen extent -0.15,-1.1 0.15,1.1, body extent -1.14,-1 1.14,1, height 0.94
Fiducial10-20 [mm]
  round 1 smd mask+0.5: 1(0,0)
  Top Layer keep-out circle w1.178: c0,0 r0.5
HDR100_1X8 [mil]
  rect 60x60 hole 38: 1(0,0) 2(100,0) 3(200,0) 4(300,0) 5(400,0) 6(500,0) 7(600,0) 8(700,0)
HEADER_NPTC202KFM [mm]
  rect 1x2 smd: 1(-11.43,-2.807) 2(-11.43,2.807) 3(-8.89,-2.807) 4(-8.89,2.807) 5(-6.35,-2.807) 6(-6.35,2.807) 7(-3.81,-2.807) 8(-3.81,2.807) 9(-1.27,-2.807) 10(-1.27,2.807) 11(1.27,-2.807) 12(1.27,2.807) 13(3.81,-2.807) 14(3.81,2.807) 15(6.35,-2.807) 16(6.35,2.807) 17(8.89,-2.807) 18(8.89,2.807) 19(11.43,-2.807) 20(11.43,2.807)
Johnson_142-0701-20x [mil] "Johnson Components recommended land pattern"
  round 95 hole 62: 1(0,0)
  round 100 hole 67: 2(100,100) 3(100,-100) 4(-100,-100) 5(-100,100)
  body extent -156,-156 156,156, height 375
Keystone_1902C [mil] "Hex Standoff, 4-40 threaded, nylon"
  round 1 on Mech4: 0(0,0)
  body extent -145,-126 146,126, height 501
Label_650x200 [mil] "Thermal Transfer Label"
  round 1 on Mech13: 0(0,0)
  silkscreen extent -325,-100 325,100, body extent -326,-101 326,101, height 1
LED0603AA [mil]
  rect 32x32 smd: 1(-32.48,0) 2(32.48,0)
  silkscreen extent -129,-24 11,27
"NY PMS 440 0025 PH" [mm] "4-40 nylon screw and mounting hole"
  round 8 hole 3.2: 1(0,0)
  body extent -3.3,-3.3 3.3,3.3, height 2.69
PW0014A_N [mm] "TSOP, 14-Leads, Body 5x4.4mm, Pitch 0.65mm, IPC Medium Density"
  oval 1.7x0.35 smd: 1(-2.85,1.95) 2(-2.85,1.3) 3(-2.85,0.65) 4(-2.85,0) 5(-2.85,-0.65) 6(-2.85,-1.3) 7(-2.85,-1.95) 8(2.85,-1.95) 9(2.85,-1.3) 10(2.85,-0.65) 11(2.85,0) 12(2.85,0.65) 13(2.85,1.3) 14(2.85,1.95)
  silkscreen extent -1.7,-2.55 1.7,2.55, body extent -3.21,-2.5 3.21,2.5, height 0.98
PW16 [mil]
  rect 70x15 smd: 1(-107.3,88) 2(-107.3,62.4) 3(-107.3,36.8) 4(-107.3,11.2) 5(-107.3,-14.4) 6(-107.3,-40) 7(-107.3,-65.6) 8(-107.3,-91.2) 9(111.7,-91.3) 10(111.7,-65.7) 11(111.7,-40.1) 12(111.7,-14.5) 13(111.7,11.1) 14(111.7,36.7) 15(111.7,62.3) 16(111.7,88)
  silkscreen extent -196,125 -166,155
RGW0020A [mm] "QFN, 20-Leads, Body 5x5mm, Pitch 0.65mm, Thermal Pad 3.15x3.15mm, TI Recommended"
  oval 0.75x0.3 smd: 1(-2.325,1.3) 2(-2.325,0.65) 3(-2.325,0) 4(-2.325,-0.65) 5(-2.325,-1.3) 11(2.325,-1.3) 12(2.325,-0.65) 13(2.325,0) 14(2.325,0.65) 15(2.325,1.3)
  oval 0.3x0.75 smd: 6(-1.3,-2.325) 7(-0.65,-2.325) 8(0,-2.325) 9(0.65,-2.325) 10(1.3,-2.325) 16(1.3,2.325) 17(0.65,2.325) 18(0,2.325) 19(-0.65,2.325) 20(-1.3,2.325)
  rect 3.15x3.15 smd paste-1.575: 21(0,0)
  silkscreen extent -2.73,-2.73 2.73,2.73, body extent -2.58,-2.57 2.57,2.58, height 1.01
SMA [mm] "Molded Diode, 2-Leads, Body 4.3x2.6mm, IPC Medium Density, based on OnSemi component dimensions and land pattern"
  rect 2x2 smd: 1(-2,0) 2(2,0)
  silkscreen extent -3.66,-1.57 2.79,1.57, body extent -2.6,-1.3 2.6,1.3, height 2.42
SO8 [mil]
  rect 80x26 smd: 1(-95,75) 2(-95,25) 3(-95,-25) 4(-95,-75) 5(94,-75) 6(94,-25) 7(94,25) 8(94,75)
  silkscreen extent -200,100 -160,140
SOD-123 [mm] "On Semi recommended land pattern"
  rect 0.915x1.22 smd: 1(-1.637,0) 2(1.637,0)
  silkscreen extent -2.75,-1.17 2.03,1.17, body extent -1.93,-0.9 1.93,0.9, height 1.35
TEC_282834-2 [mm] "TEC"
  rect 1.6x1.6 hole 1.1: 1(-1.27,0)
  round 1.6 hole 1.1: 2(1.27,0)
  silkscreen extent -3.53,-3.4 2.9,3.4, body extent -2.77,-3.25 2.77,3.25, height 10.01
TI_Stacked_SolderMask_Small [mil]
  silkscreen extent -418,-98 418,98

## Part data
C1 C2 C6 C7 C8 C9 C15 C36 C37 C38 C42: "CAP, CERM, 0.1uF, 16V, +/-5%, X7R, 0603"
C3 C44 C51: "CAP, CERM, 0.1uF, 10V, +/-10%, X7R, 0603"
C4: "CAP, CERM, 10uF, 16V, +/-20%, X5R, 0603"
C5 C10 C12 C14 C21 C35: "CAP, CERM, 1uF, 10V, +/-10%, X7R, 0805"
C11 C13 C17 C18: "CAP, CERM, 0.01uF, 25V, +/-5%, C0G/NP0, 0603"
C16 C20 C23 C24 C25: "CAP, CERM, 10uF, 16V, +/-10%, X5R, 0805"
C19 C22 C39 C43 C45 C46 C49 C50: "CAP, CERM, 5600pF, 25V, +/-5%, C0G/NP0, 0603"
C26 C27 C28 C29 C30 C31 C32 C33: "CAP, CERM, 10uF, 25V, +/-20%, X5R, 0603"
C34 C52 C53 C54 C55: "CAP, CERM, 1uF, 25V, +/-10%, X7R, 0603"
C40 C41 C47 C48: "CAP, CERM, 1000pF, 25V, +/-5%, C0G/NP0, 0603"
D1: "Diode, Schottky, 60V, 1A, SMA"
D2 D3 D4 D5 D6 D7 D8: "Diode, Zener, 3.6V, 500mW, SOD-123"
FID1 FID2 FID3 FID4 FID5 FID6: "Fiducial mark.  There is nothing to buy or mount."
H1 H2 H3 H5 H6: "Machine Screw, Round, #4-40 x 1/4, Nylon, Philips panhead"
H4 H7 H8 H9 H10: "Standoff, Hex, 0.5\"L #4-40 Nylon"
J1 J2 J3 J4 J12: "Conn Term Block, 2POS, 3.5mm, TH"
J5 J6 J7 J8: "Connector, TH, SMA"
J9: "Terminal Block, 2x1, 2.54mm, TH"
J10: "Receptacle, 100mil, 3x1, TH"
J11 J14: "CONN RCPT 20POS .100 DL STR SMD"
J13: "Connector, DC Jack 2.1X5.5 mm, TH"
J15: "Header, Male 8-pin, 100mil spacing,"
LBL1: library part THT-14-423-10, "Thermal Transfer Printable Labels, 0.650\" W x 0.200\" H - 10,000 per roll"
LD1 LD2 LD3: "LED SmartLED Green 570NM"
Logo1: library part TI_Logo, "Texas Instrument Corporate Signature"
R1 R3 R4 R6 R7 R9 R10 R12 R22 R24: "RES, 3.30k ohm, 1%, 0.1W, 0603"
R2 R5 R8 R11 R23: "RES, 20.0k ohm, 1%, 0.1W, 0603"
R13: "RES, 1.00k ohm, 1%, 0.1W, 0603"
R14 R17 R20 R27 R42 R43 R44 R45 R46 R47 R53 R55 R57 R58 R59 R62 R63 R67 R68 R69 R70 R71 R72 R73 R74 R75 R76 R77 R78 R79 R80 R81 R82 R83 R84 R85 R86 R87 R88 R89 R90 R91 R92 R93 R103 R104 R105 R106 R107 R108 R109 R110 R111 R112 R113 R114 R115 R116 R117 R118 R119 R120 R121 R123 R124: "RES, 0 ohm, 5%, 0.1W, 0603"
R15 R18 R19: "RES, 1.0k ohm, 5%, 0.1W, 0603"
R16 R21 R34: "RES, 10k ohm, 5%, 0.1W, 0603"
R25 R26 R30 R31 R37 R40 R95 R98: "RES, 1.50 k, 1%, 0.1 W, 0603"
R28 R29 R32 R33 R35 R36 R38 R39 R99 R100 R101 R102: "RES, 2.00 k, 1%, 0.1 W, 0603"
R41 R94 R96 R97: "RES, 10.0 ohm, 0.1%, 0.1W, 0603"
R48 R49 R50 R51: "RES, 0.1 ohm, 1%, 0.1W, 0603"
R52 R54 R60 R61 R64 R65 R66: "RES, 47 ohm, 5%, 0.1W, 0603"
R56: "RES, 100k ohm, 1%, 0.1W, 0603"
U1 U2 U3 U4: "SENSOR CURRENT 50A 5V MOD"
U5: "20 MHz, Low Noise, RRIO, CMOS Operational Amplifier with Shutdown, 1.8 to 5.5 V, -40 to 125 degC, 5-pin SOT23 (DBV0005A), Green (RoHS & no Sb/Br)"
U6 U7 U8 U9 U10: library part LM393D, "IC, Dual Differential Comparators, 2-36 Vin"
U11: "Low-Noise, Very Low Drift, Precision VOLTAGE REFERENCE, 2.5V, D008A"
U12: "DUAL OUTPUT VOLTAGE REFERENCE 3.3V, DBV0005A"
U13: "20 MHz, Low Noise, RRIO, CMOS Operational Amplifier, 1.8 to 5.5 V, -40 to 125 degC, 14-pin SOP (PW0014A), Green (RoHS & no Sb/Br)"
U14: "Single Output LDO, 200 mA, Fixed 3.3 V Output, 2 to 5.5 V Input, with Low IQ, 5-pin SC70 (DCK), -40 to 125 degC, Green (RoHS & no Sb/Br)"
U15: "36-V, 1-A, 4.17-µVRMS, RF LDO Voltage Regulator, RGW0020A"
U16 U17: "IC ADC 12BIT 1MSPS DUAL 16TSSOP"
ZZ1 ZZ3 ZZ4: library part AssemblyNote
ZZ2: library part AssemblyNoteLabel

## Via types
v1: diameter 26, hole 12, Top Layer to Bottom Layer, tented both sides, 143 vias
v2: diameter 30, hole 16, Top Layer to Bottom Layer, tented both sides, 84 vias
v3: diameter 40, hole 20, Top Layer to Bottom Layer, tented both sides, 7 vias

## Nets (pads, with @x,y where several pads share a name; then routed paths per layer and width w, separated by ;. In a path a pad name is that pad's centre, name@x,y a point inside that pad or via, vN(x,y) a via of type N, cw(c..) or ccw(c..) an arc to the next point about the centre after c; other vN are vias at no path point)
3V3: C21.1 C34.1 J10.1 R16.2 R21.2 R57.2 R58.2 R73.2 U14.5 | length 1669.2
  Top Layer w20: v2(1571.5,2568.5) R16.2@1620,2568.5 ; R21.2@1780,2568.5 v2(1828.5,2568.5) ; R57.2@3790,2783.5 3790,2753 v1(3808,2735) ; v2(3805,2290) R58.2@3805,2333.5
  Top Layer w25: R57.2@3790,2783.5 R57.2@3794.39,2783.5
  MidLayer2 w20: v2(1571.5,2568.5) v2(1828.5,2568.5) 1940,2680 1940,3095 2110,3265 2320,3265 v2(2335,3280)
  Bottom Layer w25: v2(4445,1140) C34.1@4528.5,1140 ; v2(4445,1205) R73.2@4528.5,1205
  other v2: 2385,3280 2335,3330 2385,3330
\C\S\: J15.6 R52.2 R75.1 | length 3152.5
  Top Layer w8: v1(3540,2280) R52.2@3540,2333.5 ; v1(3785,1610) 3785,1776 3995,1986 v1(3995,2200)
  Bottom Layer w8: v1(3540,2280) 3620,2200 v1(3995,2200) 4135,2340 4135,3000 J15.6@4370,3235 ; v1(3785,1610) R75.1@4528.5,1610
